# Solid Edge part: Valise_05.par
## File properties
Author: Bernard DUMAS
Template: Normal.par
Last saved by: FR026244
Revision: 12
Application: Solid Edge
Material: Bois, Frêne
Style de face: Jaune kaki
Style de remplissage: Liège
Style virtuel: Frêne verni
Coef. of Thermal Exp: 0.0
Thermal Conductivity: 0.0
Specific Heat: 0.0
Modulus of Elasticity: 0.0
Poission's Ratio: 0.0
Yield Stress: 0.0
Ultimate Stress: 0.0
Elongation: 0.0
Densité: 460.000 kg/m^3
Précision: 0.9900
Document Number: 05
Revision: a
Project Name: Slamson
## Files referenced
..\Valise_Salmson.asm
bD:\Documents and Settings\FR026244\Mes Documents\Bernard\Slamson\Valise-Salmson\Valise_Salmson.asm
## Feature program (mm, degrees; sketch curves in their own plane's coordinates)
sketch for "unnamed Protrusion 1" plane through (0, 0, 0) normal (0, -1, 0) x-axis (1, 0, 0)
extrude "unnamed Protrusion 1" add to key point symmetric
extrude "unnamed Cutout 1" cut finite 6
extrude "Enlèvement_matière_2" cut finite 6
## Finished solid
Body 1: solid body, 10 faces, 24 edges, 16 vertices.
  Faces by surface: plane 10
  Edges by curve: line 24
Bounding box of the edges (mm): 32.208 x 850.000 x 54.000, from (421.2918, -425, 106) to (453.5, 425, 160).
Planar faces by outward normal: +y 2, +z 2, -y 2, -z 1, oblique 3
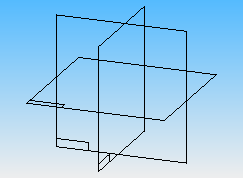
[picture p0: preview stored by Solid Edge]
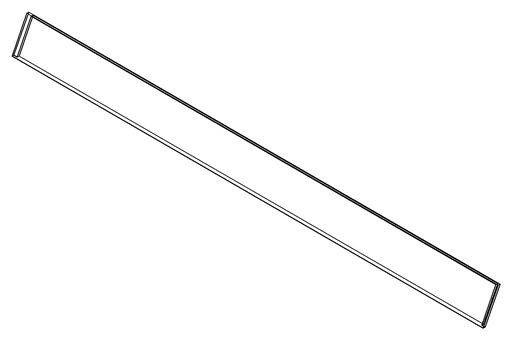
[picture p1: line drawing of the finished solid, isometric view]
